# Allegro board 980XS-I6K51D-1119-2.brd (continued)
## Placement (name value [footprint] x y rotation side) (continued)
NOREF#2058  -  []  130.05 260.06 90 top
NOREF#2059  -  []  348.03 294.87 0 top
NOREF#2060  -  []  333.22 238.82 0 top
NOREF#2061  -  []  134.23 484.32 0 top
NOREF#2062  -  []  357.14 138.77 90 top
NOREF#2063  -  []  269.86 483.75 90 top
NOREF#2064  -  []  45.9 483.76 90 top
NOREF#2065  -  []  294.81 241.35 90 top
NOREF#2066  -  []  335.38 193.86 90 top
NOREF#2067  -  []  353.99 268.8 0 top
NOREF#2068  -  []  89.64 154.45 0 top
NOREF#2069  -  []  86.59 220.75 0 top
NOREF#2070  -  []  312.91 241.11 90 top
NOREF#2071  -  []  318.6 484.4 0 top
NOREF#2072  -  []  272.46 190.23 90 top
NOREF#2073  -  []  214.38 243.29 0 top
NOREF#2074  -  []  305.33 135.72 0 top
NOREF#2075  -  []  232.26 181.11 90 top
NOREF#2076  -  []  117.42 145.37 90 top
NOREF#2077  -  []  348.03 287 0 top
NOREF#2078  -  []  354.23 187.83 0 top
NOREF#2079  -  []  92.94 220.75 0 top
NOREF#2080  -  []  322.33 173.13 90 top
NOREF#2081  -  []  473.22 237.74 0 top
NOREF#2082  -  []  295.58 242.65 90 top
NOREF#2083  -  []  334.68 195.18 0 top
NOREF#2084  -  []  251.83 206.63 0 top
NOREF#2085  -  []  482.83 224.56 0 top
NOREF#2086  -  []  157.54 483.84 90 top
NOREF#2087  -  []  336.91 181.35 90 top
NOREF#2088  -  []  260.96 187.12 90 top
NOREF#2089  -  []  271.71 184.72 0 top
NOREF#2090  -  []  508.11 209.79 90 top
NOREF#2091  -  []  311.89 246.26 0 top
NOREF#2092  -  []  304.52 288.97 0 top
NOREF#2093  -  []  347.99 241.7 0 top
NOREF#2094  -  []  251.16 247.72 90 top
NOREF#2095  -  []  540.55 192.84 90 top
NOREF#2096  -  []  314.44 146.64 0 top
NOREF#2097  -  []  307.75 172.44 90 top
NOREF#2098  -  []  268.62 244.96 0 top
NOREF#2099  -  []  506.73 230.34 0 top
NOREF#2100  -  []  293.29 193.86 90 top
NOREF#2101  -  []  109.42 238.82 0 top
NOREF#2102  -  []  312.23 227.99 0 top
NOREF#2103  -  []  267.05 135.87 0 top
NOREF#2104  -  []  482.83 161.06 0 top
NOREF#2105  -  []  230.5 181.77 90 top
NOREF#2106  -  []  549.91 154.6 0 top
NOREF#2107  -  []  86.2 263.56 90 top
NOREF#2108  -  []  311.94 247.8 0 top
NOREF#2109  -  []  541.61 150.18 0 top
NOREF#2110  -  []  315.12 299.77 90 top
NOREF#2111  -  []  273.11 243.75 90 top
NOREF#2112  -  []  230.5 183.72 90 top
NOREF#2113  -  []  271.27 179.68 90 top
NOREF#2114  -  []  356.23 163.88 90 top
NOREF#2115  -  []  87.81 164.31 90 top
NOREF#2116  -  []  223.95 233.9 90 top
NOREF#2117  -  []  211.16 236.15 90 top
NOREF#2118  -  []  271.21 245.61 0 top
NOREF#2119  -  []  118.17 484.08 0 top
NOREF#2120  -  []  255.71 193.56 0 top
NOREF#2121  -  []  314.19 483.75 90 top
NOREF#2122  -  []  353.72 183.95 90 top
NOREF#2123  -  []  233.99 208.8 0 top
NOREF#2124  -  []  85.49 154.45 0 top
NOREF#2125  -  []  117.42 177.12 90 top
NOREF#2126  -  []  333.54 190.69 90 top
NOREF#2127  -  []  549.06 197.71 90 top
NOREF#2128  -  []  211.16 251.72 0 top
NOREF#2129  -  []  33.78 484.08 0 top
NOREF#2130  -  []  275.3 190.05 0 top
NOREF#2131  -  []  122.18 202.18 0 top
NOREF#2132  -  []  348.62 244.96 0 top
NOREF#2133  -  []  228.56 238.53 90 top
NOREF#2134  -  []  351.19 269.1 90 top
NOREF#2135  -  []  233.35 250.05 0 top
NOREF#2136  -  []  261.94 484.08 0 top
NOREF#2137  -  []  124.28 201.86 90 top
NOREF#2138  -  []  270.16 185.37 90 top
NOREF#2139  -  []  141.24 484.32 0 top
NOREF#2140  -  []  227.65 259.15 90 top
NOREF#2141  -  []  377.13 467.08 0 top
NOREF#2142  -  []  481.53 256.16 90 top
NOREF#2143  -  []  223.92 299.38 0 top
NOREF#2144  -  []  473.22 240.28 0 top
NOREF#2145  -  []  350.16 184.72 90 top
NOREF#2146  -  []  104.48 201.86 90 top
NOREF#2147  -  []  294.68 183.61 0 top
NOREF#2148  -  []  270.74 181.59 0 top
NOREF#2149  -  []  474.48 138.15 0 top
NOREF#2150  -  []  80.24 189 0 top
NOREF#2151  -  []  349.96 181.3 0 top
NOREF#2152  -  []  534.31 222.55 0 top
NOREF#2153  -  []  81.82 292.7 0 top
NOREF#2154  -  []  233.43 186.02 90 top
NOREF#2155  -  []  312.35 287.13 90 top
NOREF#2156  -  []  233.56 249.57 90 top
NOREF#2157  -  []  249.31 484.08 0 top
NOREF#2158  -  []  353.68 484.4 0 top
NOREF#2159  -  []  303.27 234.06 0 top
NOREF#2160  -  []  495.12 239.96 90 top
NOREF#2161  -  []  269.28 241.06 0 top
NOREF#2162  -  []  117.24 249.7 0 top
NOREF#2163  -  []  549.55 170.72 0 top
NOREF#2164  -  []  291.16 191.72 0 top
NOREF#2165  -  []  355.12 300.55 0 top
NOREF#2166  -  []  360.83 217.63 90 top
NOREF#2167  -  []  231.61 241.11 90 top
NOREF#2168  -  []  87.91 232.41 0 top
NOREF#2169  -  []  268.03 292.21 0 top
NOREF#2170  -  []  343.27 174.06 0 top
NOREF#2171  -  []  149.12 483.84 90 top
NOREF#2172  -  []  109.42 165.47 90 top
NOREF#2173  -  []  242.24 135.14 90 top
NOREF#2174  -  []  552.28 150.18 0 top
NOREF#2175  -  []  227.25 233.9 90 top
NOREF#2176  -  []  551.91 166.3 0 top
NOREF#2177  -  []  548.24 238.75 0 top
NOREF#2178  -  []  364.9 484.4 0 top
NOREF#2179  -  []  352.26 245.64 90 top
NOREF#2180  -  []  315.44 254.76 90 top
NOREF#2181  -  []  293.16 181.35 90 top
NOREF#2182  -  []  239.77 261.38 0 top
NOREF#2183  -  []  216.91 192.91 90 top
NOREF#2184  -  []  451.08 224.56 0 top
NOREF#2185  -  []  213.61 253.56 90 top
NOREF#2186  -  []  272.46 250.23 90 top
NOREF#2187  -  []  97.99 220.6 90 top
NOREF#2188  -  []  270.5 250.23 90 top
NOREF#2189  -  []  29.57 484.08 0 top
NOREF#2190  -  []  312.05 181.59 0 top
NOREF#2191  -  []  268.67 241.94 0 top
NOREF#2192  -  []  272.7 250.05 0 top
NOREF#2193  -  []  309.25 134 0 top
NOREF#2194  -  []  227.21 259.8 90 top
NOREF#2195  -  []  260.96 247.12 90 top
NOREF#2196  -  []  551.12 169.94 90 top
NOREF#2197  -  []  351.02 185.37 0 top
NOREF#2198  -  []  115.04 154.45 0 top
NOREF#2199  -  []  346.63 247.43 0 top
NOREF#2200  -  []  387.08 462.53 90 top
NOREF#2201  -  []  348.44 202.36 0 top
NOREF#2202  -  []  195.75 287.03 90 top
NOREF#2203  -  []  258.44 299.07 0 top
NOREF#2204  -  []  293.86 252.91 90 top
NOREF#2205  -  []  346.84 149.01 0 top
NOREF#2206  -  []  214.68 193.86 90 top
NOREF#2207  -  []  345.94 203.76 0 top
NOREF#2208  -  []  360.83 157.63 90 top
NOREF#2209  -  []  295.71 242 0 top
NOREF#2210  -  []  332.78 250.69 90 top
NOREF#2211  -  []  227.65 262.2 90 top
NOREF#2212  -  []  281.59 484.08 0 top
NOREF#2213  -  []  259.33 256.13 0 top
NOREF#2214  -  []  316.99 483.75 90 top
NOREF#2215  -  []  314.49 182.93 90 top
NOREF#2216  -  []  293.61 182 0 top
NOREF#2217  -  []  271.08 269.73 0 top
NOREF#2218  -  []  270.13 207.46 90 top
NOREF#2219  -  []  280.37 135.17 0 top
NOREF#2220  -  []  460.48 158.26 0 top
NOREF#2221  -  []  262.56 290.86 0 top
NOREF#2222  -  []  474.43 155.06 90 top
NOREF#2223  -  []  304.41 171.76 90 top
NOREF#2224  -  []  412.61 484.4 0 top
NOREF#2225  -  []  241.8 483.75 90 top
NOREF#2226  -  []  213.61 242 90 top
NOREF#2227  -  []  294.3 250.94 90 top
NOREF#2228  -  []  354.61 297.98 90 top
NOREF#2229  -  []  238.71 141.78 90 top
NOREF#2230  -  []  345.48 173.73 90 top
NOREF#2231  -  []  353.4 298.37 0 top
NOREF#2232  -  []  355.44 194.76 90 top
NOREF#2233  -  []  316.7 297.74 0 top
NOREF#2234  -  []  225.81 260.2 90 top
NOREF#2235  -  []  362.54 140.92 0 top
NOREF#2236  -  []  103.59 183 90 top
NOREF#2237  -  []  291.64 253.86 90 top
NOREF#2238  -  []  334.31 242 0 top
NOREF#2239  -  []  352.8 247.31 90 top
NOREF#2240  -  []  471.23 190.01 0 top
NOREF#2241  -  []  288.03 484.08 0 top
NOREF#2242  -  []  195.51 286.85 0 top
NOREF#2243  -  []  232.45 243.75 90 top
NOREF#2244  -  []  236.23 223.88 90 top
NOREF#2245  -  []  37.86 248.1 0 top
NOREF#2246  -  []  346.71 185.85 0 top
NOREF#2247  -  []  347.41 134.7 0 top
NOREF#2248  -  []  345.33 133.69 0 top
NOREF#2249  -  []  58.43 249.91 90 top
NOREF#2250  -  []  522.13 145.86 90 top
NOREF#2251  -  []  312.05 178.99 0 top
NOREF#2252  -  []  458.53 221.76 0 top
NOREF#2253  -  []  85 277.93 0 top
NOREF#2254  -  []  212.54 194.22 90 top
NOREF#2255  -  []  272.22 181.15 0 top
NOREF#2256  -  []  223.09 232.9 0 top
NOREF#2257  -  []  114.29 188.2 0 top
NOREF#2258  -  []  120.02 132.32 90 top
NOREF#2259  -  []  124.28 138.36 90 top
NOREF#2260  -  []  352.8 187.32 90 top
NOREF#2261  -  []  228.25 234.12 0 top
NOREF#2262  -  []  264.24 207.14 0 top
NOREF#2263  -  []  85.83 207.09 90 top
NOREF#2264  -  []  138.44 484.32 0 top
NOREF#2265  -  []  317.14 146.64 90 top
NOREF#2266  -  []  331.34 243.29 0 top
NOREF#2267  -  []  354.82 285.62 0 top
NOREF#2268  -  []  266.63 187.43 0 top
NOREF#2269  -  []  224.41 231.76 90 top
NOREF#2270  -  []  268.62 184.96 0 top
NOREF#2271  -  []  539.84 220.07 90 top
NOREF#2272  -  []  280.83 217.63 90 top
NOREF#2273  -  []  334.29 195.5 0 top
NOREF#2274  -  []  322.33 233.13 90 top
NOREF#2275  -  []  346.54 134.08 0 top
NOREF#2276  -  []  454.13 190.01 0 top
NOREF#2277  -  []  352.45 242.42 90 top
NOREF#2278  -  []  314.1 286.98 90 top
NOREF#2279  -  []  335.58 182.65 90 top
NOREF#2280  -  []  215.56 180.9 90 top
NOREF#2281  -  []  274.49 182.93 90 top
NOREF#2282  -  []  273.63 183.41 0 top
NOREF#2283  -  []  221.62 292.95 90 top
NOREF#2284  -  []  80.94 292.32 0 top
NOREF#2285  -  []  333.99 193.86 90 top
NOREF#2286  -  []  305.05 145.8 90 top
NOREF#2287  -  []  345.14 299.77 0 top
NOREF#2288  -  []  266.63 247.43 0 top
NOREF#2289  -  []  333.86 252.91 90 top
NOREF#2290  -  []  242.33 173.13 90 top
NOREF#2291  -  []  253.86 181.35 90 top
NOREF#2292  -  []  112.42 168.57 0 top
NOREF#2293  -  []  155.27 484.32 0 top
NOREF#2294  -  []  539.45 206.74 90 top
NOREF#2295  -  []  312.57 246.5 0 top
NOREF#2296  -  []  352.13 184.72 90 top
NOREF#2297  -  []  540.55 192.84 0 top
NOREF#2298  -  []  329.82 484.4 0 top
NOREF#2299  -  []  336.21 241.35 90 top
NOREF#2300  -  []  295.76 240.75 0 top
NOREF#2301  -  []  381.74 484.4 0 top
NOREF#2302  -  []  351.8 179.17 90 top
NOREF#2303  -  []  233.63 143.53 0 top
NOREF#2304  -  []  308.62 244.96 0 top
NOREF#2305  -  []  83.21 287.52 90 top
NOREF#2306  -  []  232.22 243.1 0 top
NOREF#2307  -  []  313.63 138.2 0 top
NOREF#2308  -  []  349.3 245.2 0 top
NOREF#2309  -  []  300.81 175.6 90 top
NOREF#2310  -  []  295.49 243.29 90 top
NOREF#2311  -  []  123.06 483.84 90 top
NOREF#2312  -  []  272.46 242.42 90 top
NOREF#2313  -  []  231.13 243.92 90 top
NOREF#2314  -  []  509.02 227.5 0 top
NOREF#2315  -  []  51.72 484.4 0 top
NOREF#2316  -  []  252.66 182 0 top
NOREF#2317  -  []  351.48 185.37 90 top
NOREF#2318  -  []  224.91 173.9 0 top
NOREF#2319  -  []  350.82 240.82 90 top
NOREF#2320  -  []  348.67 241.94 0 top
NOREF#2321  -  []  85.83 175.34 90 top
NOREF#2322  -  []  254.3 190.94 90 top
NOREF#2323  -  []  466.83 158.26 0 top
NOREF#2324  -  []  279.1 143.77 0 top
NOREF#2325  -  []  333.83 483.75 90 top
NOREF#2326  -  []  343.95 234.46 90 top
NOREF#2327  -  []  568.42 149.79 0 top
NOREF#2328  -  []  462.89 232.77 90 top
NOREF#2329  -  []  139.3 483.84 90 top
NOREF#2330  -  []  273.07 243.95 90 top
NOREF#2331  -  []  59.04 273.28 0 top
NOREF#2332  -  []  310.47 184.57 90 top
NOREF#2333  -  []  226.84 149.01 0 top
NOREF#2334  -  []  294.36 193.12 0 top
NOREF#2335  -  []  114.64 483.84 90 top
NOREF#2336  -  []  236.16 249.57 90 top
NOREF#2337  -  []  561.7 154.99 0 top
NOREF#2338  -  []  155.45 484.08 0 top
NOREF#2339  -  []  282.24 135.14 90 top
NOREF#2340  -  []  270.06 484.4 0 top
NOREF#2341  -  []  213.86 181.35 90 top
NOREF#2342  -  []  539.84 233.33 0 top
NOREF#2343  -  []  493.92 142.82 0 top
NOREF#2344  -  []  109.42 175.32 0 top
NOREF#2345  -  []  395.56 483.75 90 top
NOREF#2346  -  []  211.96 193.56 0 top
NOREF#2347  -  []  275.48 297.35 0 top
NOREF#2348  -  []  236.7 296.96 90 top
NOREF#2349  -  []  463.78 256.31 0 top
NOREF#2350  -  []  214.31 193.56 0 top
NOREF#2351  -  []  356.48 484.4 0 top
NOREF#2352  -  []  293.34 484.4 0 top
NOREF#2353  -  []  348.93 208.11 0 top
NOREF#2354  -  []  66.13 268.47 0 top
NOREF#2355  -  []  401.33 417.57 90 top
NOREF#2356  -  []  104.48 233.61 90 top
NOREF#2357  -  []  485.88 190.01 0 top
NOREF#2358  -  []  331.34 254.86 0 top
NOREF#2359  -  []  232.26 241.11 90 top
NOREF#2360  -  []  252.33 182.3 90 top
NOREF#2361  -  []  226.36 254.55 90 top
NOREF#2362  -  []  495.12 142.17 90 top
NOREF#2363  -  []  264.52 286.43 0 top
NOREF#2364  -  []  227.99 241.05 0 top
NOREF#2365  -  []  85.49 249.7 0 top
NOREF#2366  -  []  312.26 245.64 90 top
NOREF#2367  -  []  317.14 141.43 90 top
NOREF#2368  -  []  335.16 239.65 90 top
NOREF#2369  -  []  316.11 224.14 90 top
NOREF#2370  -  []  309.94 245.61 0 top
NOREF#2371  -  []  80 276 90 top
NOREF#2372  -  []  255.56 240.9 90 top
NOREF#2373  -  []  137.21 484.08 0 top
NOREF#2374  -  []  318.39 141.02 0 top
NOREF#2375  -  []  272.26 245.64 90 top
NOREF#2376  -  []  254.29 195.5 0 top
NOREF#2377  -  []  211.64 253.86 90 top
NOREF#2378  -  []  483.26 204.13 90 top
NOREF#2379  -  []  311.11 296.5 90 top
NOREF#2380  -  []  254.29 183.93 0 top
NOREF#2381  -  []  120.64 251.7 0 top
NOREF#2382  -  []  306.84 148.23 90 top
NOREF#2383  -  []  293.14 483.75 90 top
NOREF#2384  -  []  104.66 162.15 0 top
NOREF#2385  -  []  228.09 268.12 0 top
NOREF#2386  -  []  197.77 286.37 90 top
NOREF#2387  -  []  344.09 172.66 0 top
NOREF#2388  -  []  256.21 181.35 90 top
NOREF#2389  -  []  251.16 236.15 90 top
NOREF#2390  -  []  398.74 466.58 90 top
NOREF#2391  -  []  504.01 229.58 0 top
NOREF#2392  -  []  480.78 218.56 90 top
NOREF#2393  -  []  310.55 134.62 90 top
NOREF#2394  -  []  116.75 165.57 90 top
NOREF#2395  -  []  351.89 184.96 0 top
NOREF#2396  -  []  311.26 187.56 0 top
NOREF#2397  -  []  265.85 484.4 0 top
NOREF#2398  -  []  272.13 244.72 90 top
NOREF#2399  -  []  349.53 241.46 90 top
NOREF#2400  -  []  232.23 227.99 90 top
NOREF#2401  -  []  312.45 183.76 90 top
NOREF#2402  -  []  335.38 242.3 90 top
NOREF#2403  -  []  308.25 173.12 0 top
NOREF#2404  -  []  325.91 484.08 0 top
NOREF#2405  -  []  316.16 249.57 90 top
NOREF#2406  -  []  296.15 484.4 0 top
NOREF#2407  -  []  115.04 217.95 0 top
NOREF#2408  -  []  292.78 190.69 90 top
NOREF#2409  -  []  104.48 138.36 90 top
NOREF#2410  -  []  255.56 192.47 90 top
NOREF#2411  -  []  339.72 296.97 0 top
NOREF#2412  -  []  470.13 192.81 0 top
NOREF#2413  -  []  311.16 181.77 90 top
NOREF#2414  -  []  291.64 183.61 0 top
NOREF#2415  -  []  454.13 253.51 0 top
NOREF#2416  -  []  251.16 191.72 0 top
NOREF#2417  -  []  102.24 192.89 90 top
NOREF#2418  -  []  49.21 484.08 0 top
NOREF#2419  -  []  474.12 177.11 0 top
NOREF#2420  -  []  294.81 181.35 90 top
NOREF#2421  -  []  213.22 178.82 0 top
NOREF#2422  -  []  474.43 218.56 90 top
NOREF#2423  -  []  307.57 245.37 90 top
NOREF#2424  -  []  473.22 174.24 0 top
NOREF#2425  -  []  534.61 235.83 0 top
NOREF#2426  -  []  355.29 190.05 0 top
NOREF#2427  -  []  263.09 234.38 0 top
NOREF#2428  -  []  273.3 268.63 90 top
NOREF#2429  -  []  463.17 137.52 90 top
NOREF#2430  -  []  253.1 251.59 0 top
NOREF#2431  -  []  277.08 484.4 0 top
NOREF#2432  -  []  307.75 232.44 90 top
NOREF#2433  -  []  474 165.84 0 top
NOREF#2434  -  []  263.34 202.36 90 top
NOREF#2435  -  []  234.44 144.1 0 top
NOREF#2436  -  []  228.67 241.29 0 top
NOREF#2437  -  []  351.89 186.26 0 top
NOREF#2438  -  []  108.69 186.2 0 top
NOREF#2439  -  []  34.88 484.4 0 top
NOREF#2440  -  []  227.99 181.06 0 top
NOREF#2441  -  []  391.36 483.75 90 top
NOREF#2442  -  []  380.63 484.08 0 top
NOREF#2443  -  []  217.83 192.37 0 top
NOREF#2444  -  []  266.45 147.01 90 top
NOREF#2445  -  []  340.96 175.55 90 top
NOREF#2446  -  []  90.89 214.75 90 top
NOREF#2447  -  []  344.24 207.14 0 top
NOREF#2448  -  []  66.31 250.3 0 top
NOREF#2449  -  []  534.31 231.31 0 top
NOREF#2450  -  []  485.26 143.13 0 top
NOREF#2451  -  []  540.94 220.27 0 top
NOREF#2452  -  []  355.52 467.08 0 top
NOREF#2453  -  []  347.7 249.57 90 top
NOREF#2454  -  []  62.64 484.08 0 top
NOREF#2455  -  []  268.17 137.2 90 top
NOREF#2456  -  []  560.92 147.59 90 top
NOREF#2457  -  []  511.12 228.63 90 top
NOREF#2458  -  []  474.43 250.31 90 top
NOREF#2459  -  []  296.21 241.35 90 top
NOREF#2460  -  []  272.9 249.57 90 top
NOREF#2461  -  []  553.49 146.81 90 top
NOREF#2462  -  []  456.13 256.16 90 top
NOREF#2463  -  []  222.95 290.44 90 top
NOREF#2464  -  []  99.44 296.21 90 top
NOREF#2465  -  []  335.56 192.47 90 top
NOREF#2466  -  []  311.48 186.67 90 top
NOREF#2467  -  []  231.81 239.17 90 top
NOREF#2468  -  []  544.41 164.1 90 top
NOREF#2469  -  []  277.14 146.64 90 top
NOREF#2470  -  []  332.33 193.86 90 top
NOREF#2471  -  []  480.26 201.03 90 top
NOREF#2472  -  []  480.26 232.78 90 top
NOREF#2473  -  []  31.87 483.76 90 top
NOREF#2474  -  []  403.98 483.75 90 top
NOREF#2475  -  []  331.83 206.63 0 top
NOREF#2476  -  []  266.71 245.85 0 top
NOREF#2477  -  []  227.65 259.85 90 top
NOREF#2478  -  []  263.09 172.9 0 top
NOREF#2479  -  []  90.33 193.86 0 top
NOREF#2480  -  []  332.33 253.86 90 top
NOREF#2481  -  []  297.83 192.37 0 top
NOREF#2482  -  []  526.57 483.76 90 top
NOREF#2483  -  []  295.49 183.29 90 top
NOREF#2484  -  []  356.52 134.08 90 top
NOREF#2485  -  []  456.33 190.01 0 top
NOREF#2486  -  []  348.67 181.95 0 top
NOREF#2487  -  []  268.25 173.12 0 top
NOREF#2488  -  []  273.56 189.57 90 top
NOREF#2489  -  []  371.92 484.4 0 top
NOREF#2490  -  []  333.29 242.3 90 top
NOREF#2491  -  []  351.39 250.05 0 top
NOREF#2492  -  []  214.68 255.18 0 top
NOREF#2493  -  []  111.99 252.5 0 top
NOREF#2494  -  []  402.58 483.75 90 top
NOREF#2495  -  []  382.94 483.75 90 top
NOREF#2496  -  []  251.64 183.61 0 top
NOREF#2497  -  []  458.75 173.99 90 top
NOREF#2498  -  []  458.47 205.74 90 top
NOREF#2499  -  []  271.4 246.12 0 top
NOREF#2500  -  []  373.32 484.4 0 top
NOREF#2501  -  []  237.95 138.45 90 top
NOREF#2502  -  []  38.32 299.45 0 top
NOREF#2503  -  []  227.09 266.12 0 top
NOREF#2504  -  []  352.91 181.11 90 top
NOREF#2505  -  []  266.91 146.64 0 top
NOREF#2506  -  []  303.09 174.94 0 top
NOREF#2507  -  []  251.64 182.3 90 top
NOREF#2508  -  []  377.32 483.75 90 top
NOREF#2509  -  []  233.63 138.2 0 top
NOREF#2510  -  []  228.15 242.25 0 top
NOREF#2511  -  []  212.96 254.76 0 top
NOREF#2512  -  []  37.68 268.47 0 top
NOREF#2513  -  []  59.94 169.53 0 top
NOREF#2514  -  []  274.75 286.43 0 top
NOREF#2515  -  []  273.17 296.17 0 top
NOREF#2516  -  []  354.61 298.76 0 top
NOREF#2517  -  []  310.7 269.35 90 top
NOREF#2518  -  []  310.41 180.16 0 top
NOREF#2519  -  []  117.42 240.62 90 top
NOREF#2520  -  []  214.36 241.55 0 top
NOREF#2521  -  []  392.74 467.68 0 top
NOREF#2522  -  []  533.52 484.08 0 top
NOREF#2523  -  []  266.54 133.3 90 top
NOREF#2524  -  []  256.33 484.08 0 top
NOREF#2525  -  []  127.82 484.32 0 top
NOREF#2526  -  []  551.12 153.43 90 top
NOREF#2527  -  []  358.57 231.63 90 top
NOREF#2528  -  []  227.56 144.79 0 top
NOREF#2529  -  []  311.4 181.59 0 top
NOREF#2530  -  []  309.85 244.37 90 top
NOREF#2531  -  []  309.46 145.44 90 top
NOREF#2532  -  []  272.46 182.42 90 top
NOREF#2533  -  []  226.85 190.05 0 top
NOREF#2534  -  []  58.01 254.72 0 top
NOREF#2535  -  []  241.34 136.1 0 top
NOREF#2536  -  []  315.44 194.76 90 top
NOREF#2537  -  []  271.4 181.59 0 top
NOREF#2538  -  []  458.37 231.62 90 top
NOREF#2539  -  []  260.83 211.63 0 top
NOREF#2540  -  []  291.83 206.63 0 top
NOREF#2541  -  []  510.78 232.86 0 top
NOREF#2542  -  []  398.57 484.4 0 top
NOREF#2543  -  []  533.22 484.4 0 top
NOREF#2544  -  []  333.61 193.56 0 top
NOREF#2545  -  []  230.48 184.57 90 top
NOREF#2546  -  []  306.91 146.64 0 top
NOREF#2547  -  []  355.52 466.58 90 top
NOREF#2548  -  []  319.1 142.99 90 top
NOREF#2549  -  []  277.38 484.08 0 top
NOREF#2550  -  []  271.16 186.31 90 top
NOREF#2551  -  []  354.23 247.83 0 top
NOREF#2552  -  []  49.74 249.13 90 top
NOREF#2553  -  []  252.78 250.69 90 top
NOREF#2554  -  []  262.95 292.35 90 top
NOREF#2555  -  []  314.95 182.76 0 top
NOREF#2556  -  []  475.32 239.96 90 top
NOREF#2557  -  []  214.31 242 90 top
NOREF#2558  -  []  311.8 190.23 90 top
NOREF#2559  -  []  55.64 250.3 0 top
NOREF#2560  -  []  309.96 241.3 0 top
NOREF#2561  -  []  291.64 195.18 0 top
NOREF#2562  -  []  293.1 191.59 0 top
NOREF#2563  -  []  357.95 143.66 90 top
NOREF#2564  -  []  215.56 192.47 90 top
NOREF#2565  -  []  211.96 253.56 90 top
NOREF#2566  -  []  290.54 484.4 0 top
NOREF#2567  -  []  255.71 253.56 0 top
NOREF#2568  -  []  268.03 287 0 top
NOREF#2569  -  []  312.22 241.15 0 top
NOREF#2570  -  []  310.01 270.51 0 top
NOREF#2571  -  []  57.83 272.89 0 top
NOREF#2572  -  []  211.64 255.18 0 top
NOREF#2573  -  []  547.34 225.47 0 top
NOREF#2574  -  []  349.83 269.1 90 top
NOREF#2575  -  []  253.16 181.35 90 top
NOREF#2576  -  []  307.66 185.09 0 top
NOREF#2577  -  []  348.01 233.3 90 top
NOREF#2578  -  []  116.42 191.22 90 top
NOREF#2579  -  []  277.44 193.76 90 top
NOREF#2580  -  []  397.89 462.53 90 top
NOREF#2581  -  []  291.94 484.4 0 top
NOREF#2582  -  []  471.23 221.76 0 top
NOREF#2583  -  []  110.69 157.1 90 top
NOREF#2584  -  []  119.44 249.7 0 top
NOREF#2585  -  []  366.3 484.4 0 top
NOREF#2586  -  []  86.2 278.73 90 top
NOREF#2587  -  []  123.08 173.3 0 top
NOREF#2588  -  []  377.13 466.58 90 top
NOREF#2589  -  []  339.12 300.75 0 top
NOREF#2590  -  []  483.93 158.26 0 top
NOREF#2591  -  []  226.63 181.83 90 top
NOREF#2592  -  []  305.43 295.89 90 top
NOREF#2593  -  []  258.17 209.61 90 top
NOREF#2594  -  []  355.13 183 0 top
NOREF#2595  -  []  232.21 244.43 0 top
NOREF#2596  -  []  230.26 184.4 0 top
NOREF#2597  -  []  116.42 222.97 90 top
NOREF#2598  -  []  334.81 181.35 90 top
NOREF#2599  -  []  493.02 237.74 0 top
NOREF#2600  -  []  339.33 196.13 0 top
NOREF#2601  -  []  314.69 484.08 0 top
NOREF#2602  -  []  308.52 184.61 90 top
NOREF#2603  -  []  266.91 141.04 90 top
NOREF#2604  -  []  343.34 202.36 90 top
NOREF#2605  -  []  227.57 185.37 90 top
NOREF#2606  -  []  223.95 173.9 90 top
NOREF#2607  -  []  236.11 164.14 90 top
NOREF#2608  -  []  314.44 141.43 0 top
NOREF#2609  -  []  275.44 194.76 90 top
NOREF#2610  -  []  229.69 136.26 90 top
NOREF#2611  -  []  228.95 259.88 0 top
NOREF#2612  -  []  251.34 254.86 0 top
NOREF#2613  -  []  303.95 234.46 90 top
NOREF#2614  -  []  294.42 178.17 90 top
NOREF#2615  -  []  102.36 225.12 90 top
NOREF#2616  -  []  295.56 252.47 90 top
NOREF#2617  -  []  298.75 483.75 90 top
NOREF#2618  -  []  286.33 484.4 0 top
NOREF#2619  -  []  334.29 255.5 0 top
NOREF#2620  -  []  381.93 467.68 0 top
NOREF#2621  -  []  334.68 193.86 90 top
NOREF#2622  -  []  310.26 244.4 0 top
NOREF#2623  -  []  152.65 484.08 0 top
NOREF#2624  -  []  26.26 483.76 90 top
NOREF#2625  -  []  255.51 252.91 90 top
NOREF#2626  -  []  212.33 253.86 90 top
NOREF#2627  -  []  228.09 268.12 0 top
NOREF#2628  -  []  259.9 268.32 90 top
NOREF#2629  -  []  406.79 483.75 90 top
NOREF#2630  -  []  211.16 240.15 0 top
NOREF#2631  -  []  230.7 209.35 90 top
NOREF#2632  -  []  547.86 198.36 0 top
NOREF#2633  -  []  247.41 483.75 90 top
NOREF#2634  -  []  342.22 296.45 90 top
NOREF#2635  -  []  349.47 484.4 0 top
NOREF#2636  -  []  92.33 133.71 90 top
NOREF#2637  -  []  509.02 228.95 0 top
NOREF#2638  -  []  266.84 149.01 0 top
NOREF#2639  -  []  275.97 484.08 0 top
NOREF#2640  -  []  349.28 181.06 0 top
NOREF#2641  -  []  346.03 185.61 0 top
NOREF#2642  -  []  353.72 243.95 90 top
NOREF#2643  -  []  225.33 135.72 0 top
NOREF#2644  -  []  272.57 186.5 0 top
NOREF#2645  -  []  558.12 147.98 0 top
NOREF#2646  -  []  478.78 192.01 0 top
NOREF#2647  -  []  21.15 484.08 0 top
NOREF#2648  -  []  239.1 142.99 90 top
NOREF#2649  -  []  232.26 249.57 90 top
NOREF#2650  -  []  314.61 299.77 0 top
NOREF#2651  -  []  534.31 218.36 0 top
NOREF#2652  -  []  312.46 250.23 90 top
NOREF#2653  -  []  310.5 243.72 90 top
NOREF#2654  -  []  224.52 287.7 90 top
NOREF#2655  -  []  280.91 483.84 90 top
NOREF#2656  -  []  235.12 298.76 90 top
NOREF#2657  -  []  309.04 201.34 90 top
NOREF#2658  -  []  291.16 236.15 90 top
NOREF#2659  -  []  483.31 130.58 90 top
NOREF#2660  -  []  223.27 234.62 0 top
NOREF#2661  -  []  314.39 484.4 0 top
NOREF#2662  -  []  299.72 296.97 0 top
NOREF#2663  -  []  332.63 484.4 0 top
NOREF#2664  -  []  106.74 217.95 0 top
NOREF#2665  -  []  82.01 274.46 0 top
NOREF#2666  -  []  254.93 484.08 0 top
NOREF#2667  -  []  293.1 180.02 0 top
NOREF#2668  -  []  236.59 261.82 0 top
NOREF#2669  -  []  251.34 183.29 0 top
NOREF#2670  -  []  547.34 235.63 0 top
NOREF#2671  -  []  293.54 190.69 90 top
NOREF#2672  -  []  311.11 297.8 90 top
NOREF#2673  -  []  254.31 253.56 0 top
NOREF#2674  -  []  294.31 242 0 top
NOREF#2675  -  []  397.94 462.48 90 top
NOREF#2676  -  []  354.82 284.84 90 top
NOREF#2677  -  []  313.63 143.53 0 top
NOREF#2678  -  []  355.19 268.15 90 top
NOREF#2679  -  []  301.82 296.65 90 top
NOREF#2680  -  []  291.83 266.63 0 top
NOREF#2681  -  []  213.22 240.02 0 top
NOREF#2682  -  []  251.64 242.3 90 top
NOREF#2683  -  []  229.18 178.73 90 top
NOREF#2684  -  []  26.46 484.4 0 top
NOREF#2685  -  []  351.8 190.23 90 top
NOREF#2686  -  []  105.64 157.25 0 top
NOREF#2687  -  []  211.64 183.61 0 top
NOREF#2688  -  []  97.76 165.86 0 top
NOREF#2689  -  []  292.54 194.22 90 top
NOREF#2690  -  []  387.13 462.48 90 top
NOREF#2691  -  []  280.04 135.47 90 top
NOREF#2692  -  []  461.73 218.56 90 top
NOREF#2693  -  []  270.74 190.05 0 top
NOREF#2694  -  []  231.13 183.92 90 top
NOREF#2695  -  []  268.25 174.12 0 top
NOREF#2696  -  []  369.83 263.63 90 top
NOREF#2697  -  []  331.96 242 0 top
NOREF#2698  -  []  222.56 290.86 0 top
NOREF#2699  -  []  335.09 266.49 0 top
NOREF#2700  -  []  271.27 185.2 0 top
NOREF#2701  -  []  251.64 195.18 0 top
NOREF#2702  -  []  91.44 274.57 0 top
NOREF#2703  -  []  271.19 269.1 90 top
NOREF#2704  -  []  63.39 272.5 0 top
NOREF#2705  -  []  230.16 185.37 90 top
NOREF#2706  -  []  227.95 261.38 0 top
NOREF#2707  -  []  331.16 180.15 0 top
NOREF#2708  -  []  241.08 263.12 90 top
NOREF#2709  -  []  549.06 209.01 90 top
NOREF#2710  -  []  481.73 221.76 0 top
NOREF#2711  -  []  478.78 223.76 0 top
NOREF#2712  -  []  331.34 183.29 0 top
NOREF#2713  -  []  234.91 224.78 0 top
NOREF#2714  -  []  351.6 189.57 90 top
NOREF#2715  -  []  360.99 484.08 0 top
NOREF#2716  -  []  314.49 242.93 90 top
NOREF#2717  -  []  229.53 241.46 90 top
NOREF#2718  -  []  81.69 288.47 90 top
NOREF#2719  -  []  356.7 296.96 90 top
NOREF#2720  -  []  229.53 181.46 90 top
NOREF#2721  -  []  315.12 300.55 0 top
NOREF#2722  -  []  381.73 462.48 90 top
NOREF#2723  -  []  234.44 146.64 0 top
NOREF#2724  -  []  240.37 135.17 0 top
NOREF#2725  -  []  454.13 158.26 0 top
NOREF#2726  -  []  254.36 193.12 0 top
NOREF#2727  -  []  460.89 197.67 0 top
NOREF#2728  -  []  220.81 175.6 90 top
NOREF#2729  -  []  253.22 190.39 0 top
NOREF#2730  -  []  331.64 193.86 90 top
NOREF#2731  -  []  331.96 182 0 top
NOREF#2732  -  []  240.6 484.4 0 top
NOREF#2733  -  []  470.13 224.56 0 top
NOREF#2734  -  []  313.73 243.95 90 top
NOREF#2735  -  []  256.91 241.35 90 top
NOREF#2736  -  []  352.86 244.43 0 top
NOREF#2737  -  []  381.53 483.75 90 top
NOREF#2738  -  []  305.14 299.77 0 top
NOREF#2739  -  []  331.23 484.4 0 top
NOREF#2740  -  []  511.12 230.08 90 top
NOREF#2741  -  []  379.23 484.08 0 top
NOREF#2742  -  []  263.04 484.4 0 top
NOREF#2743  -  []  255.51 181.35 90 top
NOREF#2744  -  []  102.34 186.2 0 top
NOREF#2745  -  []  559.22 133.8 90 top
NOREF#2746  -  []  49.56 265.1 90 top
NOREF#2747  -  []  240.83 157.63 90 top
NOREF#2748  -  []  315.19 208.15 90 top
NOREF#2749  -  []  318.9 484.08 0 top
NOREF#2750  -  []  273.11 190.23 90 top
NOREF#2751  -  []  348.01 234.3 90 top
NOREF#2752  -  []  315.91 224.78 0 top
NOREF#2753  -  []  312.23 167.99 0 top
NOREF#2754  -  []  525.17 483.76 90 top
NOREF#2755  -  []  117.42 208.87 90 top
NOREF#2756  -  []  271.69 269.1 0 top
NOREF#2757  -  []  458.65 149.38 0 top
NOREF#2758  -  []  219.33 256.13 0 top
NOREF#2759  -  []  43.3 484.4 0 top
NOREF#2760  -  []  291.96 193.56 0 top
NOREF#2761  -  []  354.44 146.64 0 top
NOREF#2762  -  []  292.78 239.12 90 top
NOREF#2763  -  []  232.46 240.47 90 top
NOREF#2764  -  []  103.28 139.01 0 top
NOREF#2765  -  []  311.15 250.23 90 top
NOREF#2766  -  []  245.95 268.97 90 top
NOREF#2767  -  []  273.63 146.07 0 top
NOREF#2768  -  []  227.75 172.44 90 top
NOREF#2769  -  []  255.38 182.3 90 top
NOREF#2770  -  []  254.3 239.37 90 top
NOREF#2771  -  []  303.92 299.38 0 top
NOREF#2772  -  []  255.56 252.47 90 top
NOREF#2773  -  []  309.61 245.05 0 top
NOREF#2774  -  []  534.23 209.54 0 top
NOREF#2775  -  []  80 290.97 90 top
NOREF#2776  -  []  225.48 233.73 90 top
NOREF#2777  -  []  491.48 255.51 0 top
NOREF#2778  -  []  313.63 146.07 0 top
NOREF#2779  -  []  352.35 287.13 90 top
NOREF#2780  -  []  458.47 204.47 90 top
NOREF#2781  -  []  347.03 181.43 90 top
NOREF#2782  -  []  271.26 247.56 0 top
NOREF#2783  -  []  309.23 208.44 0 top
NOREF#2784  -  []  95.99 217.95 0 top
NOREF#2785  -  []  353.07 242.62 90 top
NOREF#2786  -  []  153.87 484.32 0 top
NOREF#2787  -  []  277.95 143.66 90 top
NOREF#2788  -  []  213.39 183.61 0 top
NOREF#2789  -  []  349.53 180.81 90 top
NOREF#2790  -  []  352.57 186.5 0 top
NOREF#2791  -  []  326.81 483.75 90 top
NOREF#2792  -  []  27.66 483.76 90 top
NOREF#2793  -  []  475.32 144.71 90 top
NOREF#2794  -  []  213.32 12.42 90 top
NOREF#2795  -  []  227.95 260.68 0 top
NOREF#2796  -  []  279.73 186.59 0 top
NOREF#2797  -  []  307.25 233.9 90 top
NOREF#2798  -  []  482.83 256.31 0 top
NOREF#2799  -  []  366.32 467.08 0 top
NOREF#2800  -  []  231.08 209.73 0 top
NOREF#2801  -  []  311.27 239.68 90 top
NOREF#2802  -  []  94.04 154.45 0 top
NOREF#2803  -  []  85.29 252.35 90 top
NOREF#2804  -  []  230.75 181.59 0 top
NOREF#2805  -  []  212.78 190.69 90 top
NOREF#2806  -  []  124.28 172.65 90 top
NOREF#2807  -  []  228.01 233.3 90 top
NOREF#2808  -  []  351.48 246.02 90 top
NOREF#2809  -  []  295.51 192.91 90 top
NOREF#2810  -  []  462.48 160.91 90 top
NOREF#2811  -  []  311.4 241.59 0 top
NOREF#2812  -  []  266.61 250.23 90 top
NOREF#2813  -  []  332.54 242.65 90 top
NOREF#2814  -  []  313.3 268.63 90 top
NOREF#2815  -  []  348.31 179.21 0 top
NOREF#2816  -  []  225.94 203.76 0 top
NOREF#2817  -  []  246 483.75 90 top
NOREF#2818  -  []  329.83 225.63 90 top
NOREF#2819  -  []  263.09 232.9 0 top
NOREF#2820  -  []  312.8 247.31 90 top
NOREF#2821  -  []  254.68 242.3 90 top
NOREF#2822  -  []  549.44 225.14 90 top
NOREF#2823  -  []  232.23 227.99 0 top
NOREF#2824  -  []  351.4 246.12 0 top
NOREF#2825  -  []  122.18 204.72 0 top
NOREF#2826  -  []  239.73 246.59 0 top
NOREF#2827  -  []  87.81 209.07 0 top
NOREF#2828  -  []  269.83 269.1 90 top
NOREF#2829  -  []  260.81 187.17 90 top
NOREF#2830  -  []  243.06 270.76 90 top
NOREF#2831  -  []  353.07 180.67 90 top
NOREF#2832  -  []  254.81 192.91 90 top
NOREF#2833  -  []  463.78 256.31 0 top
NOREF#2834  -  []  256.91 181.35 90 top
NOREF#2835  -  []  85 276.47 0 top
NOREF#2836  -  []  351.8 239.17 90 top
NOREF#2837  -  []  351.15 190.23 90 top
NOREF#2838  -  []  325.61 484.4 0 top
NOREF#2839  -  []  86.2 265.01 90 top
NOREF#2840  -  []  312.7 250.05 0 top
NOREF#2841  -  []  259.12 300.75 0 top
NOREF#2842  -  []  333.16 241.35 90 top
NOREF#2843  -  []  253.61 253.56 0 top
NOREF#2844  -  []  332.54 194.22 90 top
NOREF#2845  -  []  350.62 186.5 0 top
NOREF#2846  -  []  334.3 190.94 90 top
NOREF#2847  -  []  147.04 484.08 0 top
NOREF#2848  -  []  311.89 184.89 90 top
NOREF#2849  -  []  87.81 177.32 0 top
NOREF#2850  -  []  493.02 176.78 0 top
NOREF#2851  -  []  536.86 484.4 0 top
NOREF#2852  -  []  40.79 484.08 0 top
NOREF#2853  -  []  547.34 222.67 0 top
NOREF#2854  -  []  275.06 190.23 90 top
NOREF#2855  -  []  271.4 241.59 0 top
NOREF#2856  -  []  522.57 484.4 0 top
NOREF#2857  -  []  240.04 135.47 90 top
NOREF#2858  -  []  85.87 267.8 0 top
NOREF#2859  -  []  344.71 466.58 90 top
NOREF#2860  -  []  230.16 245.37 90 top
NOREF#2861  -  []  254.42 483.75 90 top
NOREF#2862  -  []  227.65 260.55 90 top
NOREF#2863  -  []  275.48 299.38 0 top
NOREF#2864  -  []  349.17 238.73 90 top
NOREF#2865  -  []  334.68 243.61 0 top
NOREF#2866  -  []  274.44 146.64 0 top
NOREF#2867  -  []  561.7 171.5 0 top
NOREF#2868  -  []  255.51 241.35 90 top
NOREF#2869  -  []  493.48 155.06 90 top
NOREF#2870  -  []  235.06 250.23 90 top
NOREF#2871  -  []  314.91 224.78 0 top
NOREF#2872  -  []  568.79 164.49 0 top
NOREF#2873  -  []  86.59 189 0 top
NOREF#2874  -  []  321.57 134.52 90 top
NOREF#2875  -  []  310.59 180.4 0 top
NOREF#2876  -  []  231.15 190.23 90 top
NOREF#2877  -  []  456.39 242.65 90 top
NOREF#2878  -  []  271.08 209.73 0 top
NOREF#2879  -  []  265.48 173.73 90 top
NOREF#2880  -  []  349.23 208.44 0 top
NOREF#2881  -  []  351.15 241.77 90 top
NOREF#2882  -  []  216.21 192.91 90 top
NOREF#2883  -  []  313.49 295.27 90 top
NOREF#2884  -  []  234.95 242.76 0 top
NOREF#2885  -  []  243.33 272.85 90 top
NOREF#2886  -  []  223.09 174.94 0 top
NOREF#2887  -  []  505.6 225.08 90 top
NOREF#2888  -  []  264.52 294.3 0 top
NOREF#2889  -  []  102.38 141.22 0 top
NOREF#2890  -  []  238.99 483.75 90 top
NOREF#2891  -  []  523.97 484.4 0 top
NOREF#2892  -  []  87.69 249.7 0 top
NOREF#2893  -  []  271.03 185.37 0 top
NOREF#2894  -  []  534.61 233.03 0 top
NOREF#2895  -  []  272.57 184.24 90 top
NOREF#2896  -  []  42.84 272.5 90 top
NOREF#2897  -  []  355.23 223.88 90 top
NOREF#2898  -  []  252.78 239.12 90 top
NOREF#2899  -  []  266.85 190.05 0 top
NOREF#2900  -  []  295.58 182.65 90 top
NOREF#2901  -  []  107.94 219.95 0 top
NOREF#2902  -  []  91.22 261.75 90 top
NOREF#2903  -  []  232.35 292.46 90 top
NOREF#2904  -  []  87.37 272.55 90 top
NOREF#2905  -  []  214.81 192.91 90 top
NOREF#2906  -  []  352.57 484.08 0 top
NOREF#2907  -  []  542.83 167.08 0 top
NOREF#2908  -  []  224.52 294.3 0 top
NOREF#2909  -  []  354.72 462.48 90 top
NOREF#2910  -  []  264.42 236.56 0 top
NOREF#2911  -  []  350.67 483.75 90 top
NOREF#2912  -  []  343.27 235.18 0 top
NOREF#2913  -  []  231.4 241.59 0 top
NOREF#2914  -  []  270.62 186.5 0 top
NOREF#2915  -  []  227.95 263.72 0 top
NOREF#2916  -  []  347.03 241.43 90 top
NOREF#2917  -  []  112.47 222.02 90 top
NOREF#2918  -  []  352.25 189.57 90 top
NOREF#2919  -  []  487.88 256.16 90 top
NOREF#2920  -  []  251.83 170.23 315 top
NOREF#2921  -  []  462.48 256.16 90 top
NOREF#2922  -  []  295.58 194.22 90 top
NOREF#2923  -  []  252.33 193.86 90 top
NOREF#2924  -  []  272.26 185.65 90 top
NOREF#2925  -  []  238.22 254.4 90 top
NOREF#2926  -  []  86.59 157.25 0 top
NOREF#2927  -  []  230.57 210.84 0 top
NOREF#2928  -  []  310.26 184.4 0 top
NOREF#2929  -  []  392.54 462.48 90 top
NOREF#2930  -  []  251.96 182 0 top
NOREF#2931  -  []  302.45 171.5 0 top
NOREF#2932  -  []  219.12 300.75 0 top
NOREF#2933  -  []  280.23 484.08 0 top
NOREF#2934  -  []  374.72 484.4 0 top
NOREF#2935  -  []  354.48 182.93 90 top
NOREF#2936  -  []  272.23 227.99 0 top
NOREF#2937  -  []  127.27 483.84 90 top
NOREF#2938  -  []  87.81 177.32 0 top
NOREF#2939  -  []  328.72 484.08 0 top
NOREF#2940  -  []  345.29 172.02 90 top
NOREF#2941  -  []  123.08 234.26 0 top
NOREF#2942  -  []  269.85 244.37 90 top
NOREF#2943  -  []  464.88 190.01 0 top
NOREF#2944  -  []  267.25 234.3 90 top
NOREF#2945  -  []  304.57 484.4 0 top
NOREF#2946  -  []  331.34 194.86 0 top
NOREF#2947  -  []  271.48 186.67 90 top
NOREF#2948  -  []  253.1 191.59 0 top
NOREF#2949  -  []  234.61 298.76 0 top
NOREF#2950  -  []  97.76 197.61 0 top
NOREF#2951  -  []  363.8 484.08 0 top
NOREF#2952  -  []  458.47 236.22 90 top
NOREF#2953  -  []  103.28 205.05 0 top
NOREF#2954  -  []  233.81 183.65 0 top
NOREF#2955  -  []  239.49 484.08 0 top
NOREF#2956  -  []  114.42 171.07 0 top
NOREF#2957  -  []  263.27 234.62 0 top
NOREF#2958  -  []  342.56 290.86 0 top
NOREF#2959  -  []  30.67 484.4 0 top
NOREF#2960  -  []  215.71 253.56 90 top
NOREF#2961  -  []  80.94 264.88 0 top
NOREF#2962  -  []  266.63 181.83 90 top
NOREF#2963  -  []  260.81 175.6 90 top
NOREF#2964  -  []  403.6 467.63 0 top
NOREF#2965  -  []  464.88 253.51 0 top
NOREF#2966  -  []  150.52 483.84 90 top
NOREF#2967  -  []  351.21 245.61 0 top
NOREF#2968  -  []  252.78 179.12 90 top
NOREF#2969  -  []  355.38 484.08 0 top
NOREF#2970  -  []  353.63 143.53 0 top
NOREF#2971  -  []  305.29 172.02 90 top
NOREF#2972  -  []  475.38 158.26 0 top
NOREF#2973  -  []  233.08 242.62 90 top
NOREF#2974  -  []  214.66 181.23 0 top
NOREF#2975  -  []  268.52 184.61 90 top
NOREF#2976  -  []  94.04 186.2 0 top
NOREF#2977  -  []  352.05 181.59 0 top
NOREF#2978  -  []  255.16 239.65 90 top
NOREF#2979  -  []  317.95 141.12 90 top
NOREF#2980  -  []  414.95 466.58 90 top
NOREF#2981  -  []  101.59 251.7 0 top
NOREF#2982  -  []  331.96 193.56 0 top
NOREF#2983  -  []  335.51 252.91 90 top
NOREF#2984  -  []  482.83 192.81 0 top
NOREF#2985  -  []  227 258.45 0 top
NOREF#2986  -  []  291.23 176.59 90 top
NOREF#2987  -  []  348.14 242.25 0 top
NOREF#2988  -  []  238.82 259.85 0 top
NOREF#2989  -  []  225.31 260.2 0 top
NOREF#2990  -  []  329.62 483.75 90 top
NOREF#2991  -  []  90.89 183 90 top
NOREF#2992  -  []  310.18 484.4 0 top
NOREF#2993  -  []  479.53 221.76 0 top
NOREF#2994  -  []  60.8 254.33 90 top
NOREF#2995  -  []  353.63 140.86 0 top
NOREF#2996  -  []  91.44 288.29 0 top
NOREF#2997  -  []  390.16 484.4 0 top
NOREF#2998  -  []  234.91 164.78 0 top
NOREF#2999  -  []  86.2 292.44 90 top
NOREF#3000  -  []  230.59 240.4 0 top
NOREF#3001  -  []  354.95 182.76 0 top
NOREF#3002  -  []  92.94 157.25 0 top
NOREF#3003  -  []  229.27 263.12 90 top
NOREF#3004  -  []  77.67 288.67 0 top
NOREF#3005  -  []  237.62 260.2 90 top
NOREF#3006  -  []  468.26 201.9 0 top
NOREF#3007  -  []  355.44 254.76 90 top
NOREF#3008  -  []  293.99 253.86 90 top
NOREF#3009  -  []  81.82 278.99 0 top
NOREF#3010  -  []  257.73 484.08 0 top
NOREF#3011  -  []  85 279.38 0 top
NOREF#3012  -  []  115.81 253.42 90 top
NOREF#3013  -  []  243.96 287.7 90 top
NOREF#3014  -  []  144.23 484.08 0 top
NOREF#3015  -  []  267.9 184.41 90 top
NOREF#3016  -  []  88.89 156.45 0 top
NOREF#3017  -  []  272.25 249.57 90 top
NOREF#3018  -  []  403.29 462.53 90 top
NOREF#3019  -  []  350.74 190.05 0 top
NOREF#3020  -  []  303.09 234.94 0 top
NOREF#3021  -  []  493.02 208.53 0 top
NOREF#3022  -  []  255.38 242.3 90 top
NOREF#3023  -  []  27.86 484.4 0 top
NOREF#3024  -  []  485.88 221.76 0 top
NOREF#3025  -  []  267.75 172.44 90 top
NOREF#3026  -  []  308.17 137.2 90 top
NOREF#3027  -  []  215.76 180.75 0 top
NOREF#3028  -  []  229.3 185.85 0 top
NOREF#3029  -  []  534.31 235.5 0 top
NOREF#3030  -  []  268.45 483.75 90 top
NOREF#3031  -  []  546.96 210.74 0 top
NOREF#3032  -  []  109.42 207.07 0 top
NOREF#3033  -  []  116.59 484.32 0 top
NOREF#3034  -  []  276.52 134.08 90 top
NOREF#3035  -  []  230.62 187.15 0 top
NOREF#3036  -  []  255.38 193.86 90 top
NOREF#3037  -  []  294.54 483.75 90 top
NOREF#3038  -  []  295.71 193.56 0 top
NOREF#3039  -  []  388.55 483.75 90 top
NOREF#3040  -  []  355.05 190.23 90 top
NOREF#3041  -  []  291.64 182.3 90 top
NOREF#3042  -  []  224.52 293.03 90 top
NOREF#3043  -  []  334.81 192.91 90 top
NOREF#3044  -  []  251.83 266.63 0 top
NOREF#3045  -  []  268.96 484.08 0 top
NOREF#3046  -  []  376.58 467.63 0 top
NOREF#3047  -  []  112.42 136.82 90 top
NOREF#3048  -  []  232.23 170.19 90 top
NOREF#3049  -  []  305.48 235.27 0 top
NOREF#3050  -  []  521.48 150.51 0 top
NOREF#3051  -  []  351.6 181.11 90 top
NOREF#3052  -  []  350.62 185.85 0 top
NOREF#3053  -  []  259.72 296.97 0 top
NOREF#3054  -  []  335.76 180.75 0 top
NOREF#3055  -  []  355.12 298.76 90 top
NOREF#3056  -  []  360.04 137.42 90 top
NOREF#3057  -  []  107.85 225.8 90 top
NOREF#3058  -  []  221.29 297.9 0 top
NOREF#3059  -  []  291.64 193.86 90 top
NOREF#3060  -  []  240.76 259.78 90 top
NOREF#3061  -  []  353.1 183.76 90 top
NOREF#3062  -  []  546.96 212.13 0 top
NOREF#3063  -  []  308.62 245.61 0 top
NOREF#3064  -  []  237.44 193.76 90 top
NOREF#3065  -  []  350.55 134.62 90 top
NOREF#3066  -  []  293.16 241.35 90 top
NOREF#3067  -  []  355.29 250.05 0 top
NOREF#3068  -  []  334.68 182.3 90 top
NOREF#3069  -  []  303.27 174.62 0 top
NOREF#3070  -  []  238.57 171.63 90 top
NOREF#3071  -  []  294.38 254.86 0 top
NOREF#3072  -  []  307.9 182.43 90 top
NOREF#3073  -  []  266.84 148.23 90 top
NOREF#3074  -  []  252.33 253.86 90 top
NOREF#3075  -  []  473.2 165.43 90 top
NOREF#3076  -  []  308.44 202.36 0 top
NOREF#3077  -  []  470.13 192.81 0 top
NOREF#3078  -  []  294.68 243.61 0 top
NOREF#3079  -  []  324.51 484.08 0 top
NOREF#3080  -  []  293.86 192.91 90 top
NOREF#3081  -  []  293.39 243.61 0 top
NOREF#3082  -  []  355.44 254.76 90 top
NOREF#3083  -  []  353.56 189.57 90 top
NOREF#3084  -  []  62.34 484.4 0 top
NOREF#3085  -  []  269.17 178.73 90 top
NOREF#3086  -  []  254.01 417.57 90 top
NOREF#3087  -  []  233.62 264.2 0 top
NOREF#3088  -  []  289.83 165.63 90 top
NOREF#3089  -  []  304.96 136.11 90 top
NOREF#3090  -  []  241.57 134.52 90 top
NOREF#3091  -  []  97.76 229.36 0 top
NOREF#3092  -  []  268.62 185.61 0 top
NOREF#3093  -  []  350.55 134.62 0 top
NOREF#3094  -  []  221.21 254.4 0 top
NOREF#3095  -  []  352.35 284.59 90 top
NOREF#3096  -  []  360.37 467.63 0 top
NOREF#3097  -  []  230.5 241.77 90 top
NOREF#3098  -  []  475.18 192.66 90 top
NOREF#3099  -  []  458.53 158.26 0 top
NOREF#3100  -  []  335.49 183.29 90 top
NOREF#3101  -  []  241.08 261.38 90 top
NOREF#3102  -  []  63.54 483.76 90 top
NOREF#3103  -  []  350.5 250.23 90 top
NOREF#3104  -  []  300.81 247.17 90 top
NOREF#3105  -  []  219.72 296.97 0 top
NOREF#3106  -  []  317.11 164.14 90 top
NOREF#3107  -  []  229.96 241.3 0 top
NOREF#3108  -  []  245.83 169.63 90 top
NOREF#3109  -  []  156.68 484.32 0 top
NOREF#3110  -  []  229.96 181.3 0 top
NOREF#3111  -  []  308.25 233.12 0 top
NOREF#3112  -  []  402.78 484.4 0 top
NOREF#3113  -  []  352.21 241.15 0 top
NOREF#3114  -  []  104.48 172.65 90 top
NOREF#3115  -  []  65.76 268.08 0 top
NOREF#3116  -  []  230.41 240.16 0 top
NOREF#3117  -  []  273.63 140.86 0 top
NOREF#3118  -  []  249.83 222.63 90 top
NOREF#3119  -  []  381.13 463.08 90 top
NOREF#3120  -  []  534.61 234.43 0 top
NOREF#3121  -  []  236.23 130.83 90 top
NOREF#3122  -  []  353.66 269.1 90 top
NOREF#3123  -  []  228.62 184.96 0 top
NOREF#3124  -  []  232.22 241.15 0 top
NOREF#3125  -  []  312.35 284.59 90 top
NOREF#3126  -  []  263.27 174.06 0 top
NOREF#3127  -  []  56.67 266.66 0 top
NOREF#3128  -  []  316.52 134.86 0 top
NOREF#3129  -  []  238.82 258.45 0 top
NOREF#3130  -  []  108.69 186.2 0 top
NOREF#3131  -  []  371.23 236.59 90 top
NOREF#3132  -  []  368.91 483.75 90 top
NOREF#3133  -  []  242.43 272.37 0 top
NOREF#3134  -  []  458.75 172.72 90 top
NOREF#3135  -  []  253.54 179.12 90 top
NOREF#3136  -  []  389.05 484.08 0 top
NOREF#3137  -  []  289.83 162.63 90 top
NOREF#3138  -  []  273.4 298.37 0 top
NOREF#3139  -  []  395.77 484.4 0 top
NOREF#3140  -  []  291.64 243.61 0 top
NOREF#3141  -  []  459.73 223.76 0 top
NOREF#3142  -  []  350.47 244.57 90 top
NOREF#3143  -  []  214.36 193.12 0 top
NOREF#3144  -  []  310.16 184.72 90 top
NOREF#3145  -  []  306.71 245.85 0 top
NOREF#3146  -  []  229.18 238.73 90 top
NOREF#3147  -  []  137.03 484.32 0 top
NOREF#3148  -  []  266.63 241.83 90 top
NOREF#3149  -  []  274.91 164.78 0 top
NOREF#3150  -  []  230.5 243.72 90 top
NOREF#3151  -  []  194.35 287.03 90 top
NOREF#3152  -  []  272.45 243.75 90 top
NOREF#3153  -  []  340.81 247.17 90 top
NOREF#3154  -  []  293.29 253.86 90 top
NOREF#3155  -  []  243.6 273.73 90 top
NOREF#3156  -  []  473.18 190.01 0 top
NOREF#3157  -  []  233.63 183.41 0 top
NOREF#3158  -  []  55.46 266.27 0 top
NOREF#3159  -  []  271.6 249.57 90 top
NOREF#3160  -  []  232.46 180.47 90 top
NOREF#3161  -  []  360.07 462.53 90 top
NOREF#3162  -  []  294.29 183.93 0 top
NOREF#3163  -  []  321.34 136.1 0 top
NOREF#3164  -  []  351.89 246.26 0 top
NOREF#3165  -  []  344.41 171.76 90 top
NOREF#3166  -  []  221.82 296.65 90 top
NOREF#3167  -  []  490.28 158.26 0 top
NOREF#3168  -  []  232.05 181.59 0 top
NOREF#3169  -  []  461.73 155.06 90 top
NOREF#3170  -  []  454.13 221.76 0 top
NOREF#3171  -  []  242.54 140.92 0 top
NOREF#3172  -  []  229.25 134 0 top
NOREF#3173  -  []  227.05 134.08 90 top
NOREF#3174  -  []  214.38 183.29 0 top
NOREF#3175  -  []  244.6 483.75 90 top
NOREF#3176  -  []  335.51 192.91 90 top
NOREF#3177  -  []  552.28 147.98 0 top
NOREF#3178  -  []  198.56 287.03 90 top
NOREF#3179  -  []  193.57 286.37 90 top
NOREF#3180  -  []  260.83 271.63 0 top
NOREF#3181  -  []  151.24 484.08 0 top
NOREF#3182  -  []  303.27 292.05 0 top
NOREF#3183  -  []  305.48 175.27 0 top
NOREF#3184  -  []  268.03 294.87 0 top
NOREF#3185  -  []  309.28 241.06 0 top
NOREF#3186  -  []  228.31 259.78 0 top
NOREF#3187  -  []  334.31 182 0 top
NOREF#3188  -  []  355.44 194.76 90 top
NOREF#3189  -  []  347.05 135.87 0 top
NOREF#3190  -  []  225.48 173.73 90 top
NOREF#3191  -  []  228.25 174.12 0 top
NOREF#3192  -  []  211.96 182 0 top
NOREF#3193  -  []  239.47 262.2 90 top
NOREF#3194  -  []  274.44 141.43 0 top
NOREF#3195  -  []  252.66 242 0 top
NOREF#3196  -  []  271.16 241.77 90 top
NOREF#3197  -  []  344.47 291.41 90 top
NOREF#3198  -  []  145.45 484.32 0 top
NOREF#3199  -  []  351.15 250.23 90 top
NOREF#3200  -  []  222.45 231.5 0 top
NOREF#3201  -  []  350.47 184.57 90 top
NOREF#3202  -  []  312.23 167.99 90 top
NOREF#3203  -  []  350.59 240.4 0 top
NOREF#3204  -  []  352.23 167.99 90 top
NOREF#3205  -  []  376.53 467.68 0 top
NOREF#3206  -  []  271.11 296.5 90 top
NOREF#3207  -  []  292.54 182.65 90 top
NOREF#3208  -  []  243.36 272.69 0 top
NOREF#3209  -  []  307.9 242.43 90 top
NOREF#3210  -  []  277.11 224.14 90 top
NOREF#3211  -  []  192.95 287.03 90 top
NOREF#3212  -  []  268.15 242.25 0 top
NOREF#3213  -  []  315.13 243 0 top
NOREF#3214  -  []  295.71 182 0 top
NOREF#3215  -  []  352.45 182.42 90 top
NOREF#3216  -  []  237.59 483.75 90 top
NOREF#3217  -  []  463.78 224.56 0 top
NOREF#3218  -  []  82.01 260.74 0 top
NOREF#3219  -  []  350.62 247.15 0 top
NOREF#3220  -  []  502.58 207.92 0 top
NOREF#3221  -  []  295.05 484.08 0 top
NOREF#3222  -  []  304.52 291.64 0 top
NOREF#3223  -  []  369.83 225.63 90 top
NOREF#3224  -  []  414.1 462.53 90 top
NOREF#3225  -  []  414.4 467.63 0 top
NOREF#3226  -  []  353.43 246.02 90 top
NOREF#3227  -  []  457.43 224.56 0 top
NOREF#3228  -  []  464.88 221.76 0 top
NOREF#3229  -  []  303.95 174.46 90 top
NOREF#3230  -  []  87.91 232.41 90 top
NOREF#3231  -  []  276.61 288.05 0 top
NOREF#3232  -  []  267.99 241.05 0 top
NOREF#3233  -  []  255.83 483.75 90 top
NOREF#3234  -  []  293.61 253.56 0 top
NOREF#3235  -  []  306.54 134.08 0 top
NOREF#3236  -  []  212.78 250.69 90 top
NOREF#3237  -  []  385.74 483.75 90 top
NOREF#3238  -  []  87.81 240.82 0 top
NOREF#3239  -  []  212.43 15.11 0 top
NOREF#3240  -  []  213.29 182.3 90 top
NOREF#3241  -  []  233.11 250.23 90 top
NOREF#3242  -  []  354.44 144.1 0 top
NOREF#3243  -  []  232.23 167.99 0 top
NOREF#3244  -  []  116.29 214.75 90 top
NOREF#3245  -  []  347.99 181.7 0 top
NOREF#3246  -  []  382.04 484.08 0 top
NOREF#3247  -  []  102.38 138.68 0 top
NOREF#3248  -  []  456.67 179.15 90 top
NOREF#3249  -  []  113.09 154.45 0 top
NOREF#3250  -  []  493.92 145.36 0 top
NOREF#3251  -  []  72.69 265.81 0 top
NOREF#3252  -  []  293.61 242 0 top
NOREF#3253  -  []  223.34 202.36 90 top
NOREF#3254  -  []  91.84 249.7 0 top
NOREF#3255  -  []  312.05 241.59 0 top
NOREF#3256  -  []  311.19 209.1 90 top
NOREF#3257  -  []  352.91 241.11 90 top
NOREF#3258  -  []  311.16 243.72 90 top
NOREF#3259  -  []  123.08 205.05 0 top
NOREF#3260  -  []  308.78 484.4 0 top
NOREF#3261  -  []  245.83 229.63 90 top
NOREF#3262  -  []  333.22 250.39 0 top
NOREF#3263  -  []  273.35 250.05 0 top
NOREF#3264  -  []  329.83 263.63 90 top
NOREF#3265  -  []  309.3 185.2 0 top
NOREF#3266  -  []  253.29 193.86 90 top
NOREF#3267  -  []  332.78 179.12 90 top
NOREF#3268  -  []  215.01 193.56 0 top
NOREF#3269  -  []  534.61 222.87 0 top
NOREF#3270  -  []  129.22 484.32 0 top
NOREF#3271  -  []  295.71 240.7 0 top
NOREF#3272  -  []  251.96 193.56 0 top
NOREF#3273  -  []  109.42 133.72 90 top
NOREF#3274  -  []  229.28 181.06 0 top
NOREF#3275  -  []  239.47 259.15 90 top
NOREF#3276  -  []  350.5 243.72 90 top
NOREF#3277  -  []  211.16 247.72 90 top
NOREF#3278  -  []  353.3 268.63 90 top
NOREF#3279  -  []  349.33 210.27 0 top
NOREF#3280  -  []  253.39 243.61 0 top
NOREF#3281  -  []  474.12 142.82 0 top
NOREF#3282  -  []  116.29 246.5 90 top
NOREF#3283  -  []  115.37 484.08 0 top
NOREF#3284  -  []  231.16 181.77 90 top
NOREF#3285  -  []  336.21 192.91 90 top
NOREF#3286  -  []  311.6 189.57 90 top
NOREF#3287  -  []  303.09 234.38 0 top
NOREF#3288  -  []  312.22 183.1 0 top
NOREF#3289  -  []  458.47 237.49 90 top
NOREF#3290  -  []  230.92 244.4 0 top
NOREF#3291  -  []  64.97 271.72 90 top
NOREF#3292  -  []  104.48 140.9 90 top
NOREF#3293  -  []  235.91 224.78 0 top
NOREF#3294  -  []  487.13 155.06 90 top
NOREF#3295  -  []  293.22 178.82 0 top
NOREF#3296  -  []  98.19 217.95 0 top
NOREF#3297  -  []  497.61 212.49 0 top
NOREF#3298  -  []  275.12 299.54 0 top
NOREF#3299  -  []  240.12 262.82 0 top
NOREF#3300  -  []  242.43 273.73 0 top
NOREF#3301  -  []  315.23 163.88 90 top
NOREF#3302  -  []  294.31 193.56 0 top
NOREF#3303  -  []  509.92 230.73 0 top
NOREF#3304  -  []  312.23 232.39 90 top
NOREF#3305  -  []  231.26 247.56 0 top
NOREF#3306  -  []  472.43 223.76 0 top
NOREF#3307  -  []  252.66 253.56 0 top
NOREF#3308  -  []  350.7 209.35 90 top
NOREF#3309  -  []  294.42 189.74 90 top
NOREF#3310  -  []  144.91 483.84 90 top
NOREF#3311  -  []  229.61 245.05 0 top
NOREF#3312  -  []  215.58 243.29 90 top
NOREF#3313  -  []  251.64 243.61 0 top
NOREF#3314  -  []  567.63 169.94 90 top
NOREF#3315  -  []  312.04 250.05 0 top
NOREF#3316  -  []  458.37 231.62 0 top
NOREF#3317  -  []  311.71 184.72 0 top
NOREF#3318  -  []  98.19 186.2 0 top
NOREF#3319  -  []  89.64 217.95 0 top
NOREF#3320  -  []  256.91 192.91 90 top
NOREF#3321  -  []  310.62 245.85 0 top
NOREF#3322  -  []  241.4 259.88 90 top
NOREF#3323  -  []  231.16 183.72 90 top
NOREF#3324  -  []  335.71 253.56 0 top
NOREF#3325  -  []  223.95 234.46 90 top
NOREF#3326  -  []  274.61 298.76 0 top
NOREF#3327  -  []  276.61 287.27 90 top
NOREF#3328  -  []  102.34 217.95 0 top
NOREF#3329  -  []  100.39 186.2 0 top
NOREF#3330  -  []  270.55 134.62 90 top
NOREF#3331  -  []  312.22 243.1 0 top
NOREF#3332  -  []  56.85 248.49 0 top
